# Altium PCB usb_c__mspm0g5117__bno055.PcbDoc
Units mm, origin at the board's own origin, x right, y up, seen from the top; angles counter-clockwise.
Board outline 68 x 40 mm, 2 copper layers (Top, Bottom), stack 0 mm thick; 42 components, 34 nets, 214 pads, 84 vias.
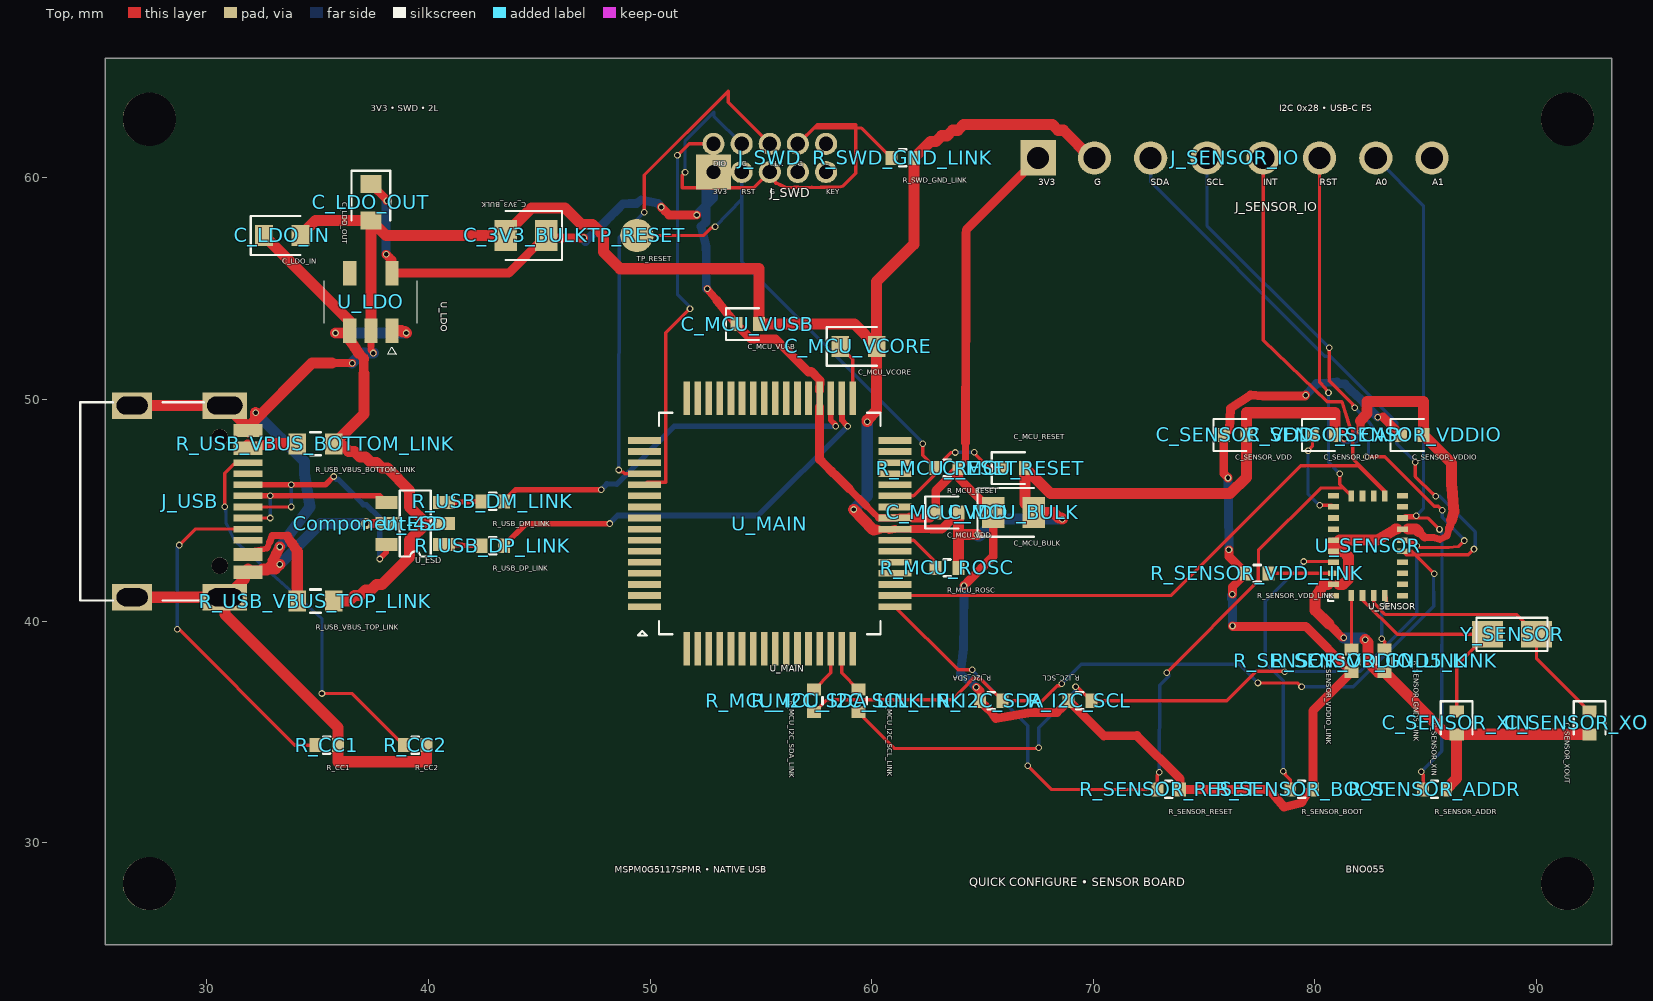
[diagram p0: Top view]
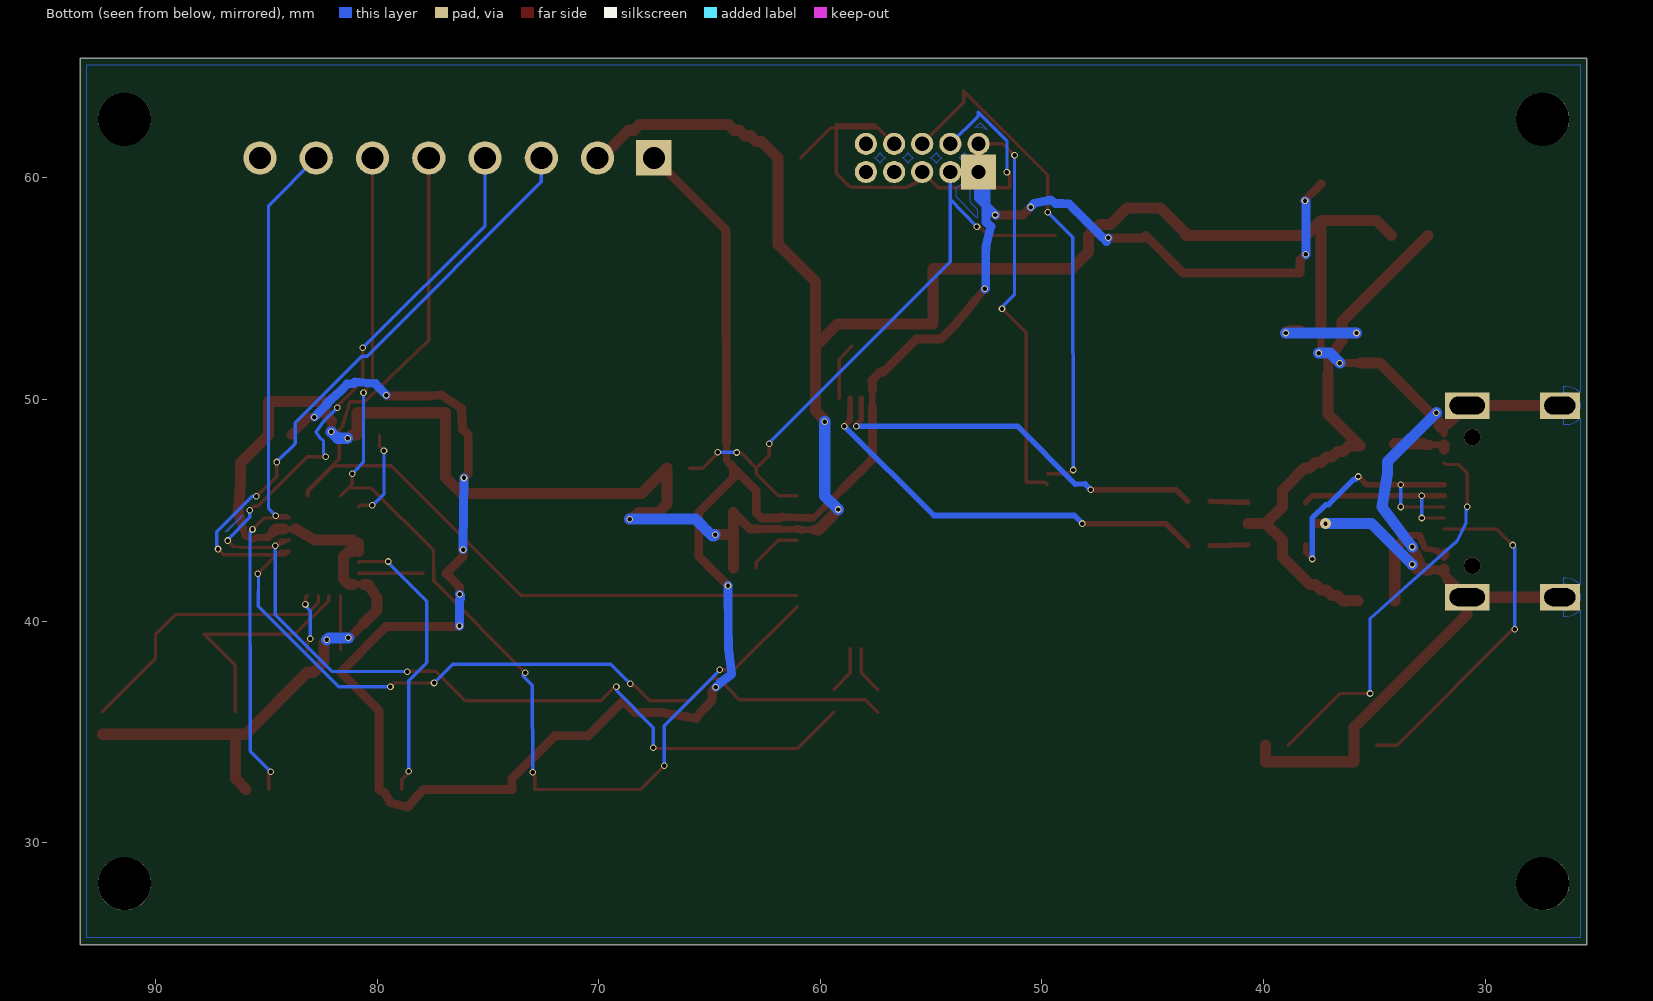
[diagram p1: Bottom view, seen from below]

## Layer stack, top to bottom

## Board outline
25.4,65.4 93.4,65.4 93.4,25.4 25.4,25.4

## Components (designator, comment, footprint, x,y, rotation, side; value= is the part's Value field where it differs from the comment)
C_3V3_BULK "" TSCIRCUIT-2.8500x1.4000mm 44.4,57.4 r180 top
C_LDO_IN "" TSCIRCUIT-2.4500x0.9500mm 33.4,57.4 r0 top
C_LDO_OUT "" TSCIRCUIT-0.9500x2.4500mm 37.4,58.9 r270 top
C_MCU_BULK "" TSCIRCUIT-2.8500x1.4000mm 66.4,44.9 r0 top
C_MCU_RESET "" TSCIRCUIT-1.5600x0.6400mm 66.4,46.9 r0 top
C_MCU_VCORE "" TSCIRCUIT-2.4500x0.9500mm 59.4,52.4 r0 top
C_MCU_VDD "" TSCIRCUIT-1.5600x0.6400mm 63.4,44.9 r0 top
C_MCU_VUSB "" TSCIRCUIT-1.5600x0.6400mm 54.4,53.4 r0 top
C_SENSOR_CAP "" TSCIRCUIT-1.5600x0.6400mm 80.4,48.4 r0 top
C_SENSOR_VDD "" TSCIRCUIT-1.5600x0.6400mm 76.4,48.4 r0 top
C_SENSOR_VDDIO "" TSCIRCUIT-1.5600x0.6400mm 84.4,48.4 r0 top
C_SENSOR_XIN "" TSCIRCUIT-0.6400x1.5600mm 86.4,35.4 r270 top
C_SENSOR_XOUT "" TSCIRCUIT-0.6400x1.5600mm 92.4,35.4 r270 top
Component-42 "" TSCIRCUIT-0.5000x0.5000mm 37.2,44.4 r0 top
J_SENSOR_IO "" TSCIRCUIT-19.2800x1.5000mm 76.4,60.9 r0 top
J_SWD "" TSCIRCUIT-6.0800x2.2700mm 55.4,60.9 r0 top
J_USB "" TSCIRCUIT-6.7732x9.8502mm 29.112,45.4 r90 top
R_CC1 "" TSCIRCUIT-1.5600x0.6400mm 35.4,34.4 r0 top
R_CC2 "" TSCIRCUIT-1.5600x0.6400mm 39.4,34.4 r0 top
R_I2C_SCL "" TSCIRCUIT-1.5600x0.6400mm 69.4,36.4 r180 top
R_I2C_SDA "" TSCIRCUIT-1.5600x0.6400mm 65.4,36.4 r180 top
R_MCU_I2C_SCL_LINK "" TSCIRCUIT-0.6400x1.5600mm 59.4,36.4 r270 top
R_MCU_I2C_SDA_LINK "" TSCIRCUIT-0.6400x1.5600mm 57.4,36.4 r270 top
R_MCU_RESET "" TSCIRCUIT-1.5600x0.6400mm 63.4,46.9 r0 top
R_MCU_ROSC "" TSCIRCUIT-1.5600x0.6400mm 63.4,42.4 r0 top
R_SENSOR_ADDR "" TSCIRCUIT-1.5600x0.6400mm 85.4,32.4 r0 top
R_SENSOR_BOOT "" TSCIRCUIT-1.5600x0.6400mm 79.4,32.4 r0 top
R_SENSOR_GND5_LINK "" TSCIRCUIT-0.6400x1.5600mm 83.15,38.2 r270 top
R_SENSOR_RESET "" TSCIRCUIT-1.5600x0.6400mm 73.4,32.4 r0 top
R_SENSOR_VDD_LINK "" TSCIRCUIT-1.5600x0.6400mm 77.4,42.15 r0 top
R_SENSOR_VDDIO_LINK "" TSCIRCUIT-0.6400x1.5600mm 81.65,38.2 r270 top
R_SWD_GND_LINK "" TSCIRCUIT-1.5600x0.6400mm 61.4,60.9 r0 top
R_USB_DM_LINK "" TSCIRCUIT-1.5600x0.6400mm 42.9,45.4 r0 top
R_USB_DP_LINK "" TSCIRCUIT-1.5600x0.6400mm 42.9,43.4 r0 top
R_USB_VBUS_BOTTOM_LINK "" TSCIRCUIT-2.4500x0.9500mm 34.9,48 r0 top
R_USB_VBUS_TOP_LINK "" TSCIRCUIT-2.4500x0.9500mm 34.9,40.9 r0 top
TP_RESET "" TSCIRCUIT-1.5000x1.5000mm 49.4,57.4 r0 top
U_ESD "" TSCIRCUIT-3.6000x2.5000mm 39.4,44.4 r0 top
U_LDO "" TSCIRCUIT-2.5000x3.7000mm 37.4,54.4 r270 top
U_MAIN "" TSCIRCUIT-12.8000x12.8000mm 55.4,44.4 r0 top
U_SENSOR "" TSCIRCUIT-3.6260x4.9999mm 82.4,43.4 r0 top
Y_SENSOR "" TSCIRCUIT-3.6000x1.2000mm 88.9,39.4 r0 top

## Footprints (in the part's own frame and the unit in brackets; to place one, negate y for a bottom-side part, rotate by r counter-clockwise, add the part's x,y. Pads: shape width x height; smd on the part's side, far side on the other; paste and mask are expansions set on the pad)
TSCIRCUIT-0.5000x0.5000mm [mm]
TSCIRCUIT-0.6400x1.5600mm [mm]
  rect 0.54x0.64 smd: 1(-0.51,0) 2(0.51,0)
  silkscreen extent -0.98,-0.72 0.51,0.72
TSCIRCUIT-0.9500x2.4500mm [mm]
  rect 0.8x0.95 smd: 1(-0.825,0) 2(0.825,0)
  silkscreen extent -1.43,-0.87 0.82,0.88
TSCIRCUIT-1.5000x1.5000mm [mm]
  round 1.5 smd: 1(0,0)
TSCIRCUIT-1.5600x0.6400mm [mm]
  rect 0.54x0.64 smd: 1(-0.51,0) 2(0.51,0)
  silkscreen extent -0.98,-0.72 0.51,0.72
TSCIRCUIT-2.4500x0.9500mm [mm]
  rect 0.8x0.95 smd: 1(-0.825,0) 2(0.825,0)
  silkscreen extent -1.42,-0.87 0.82,0.87
TSCIRCUIT-2.5000x3.7000mm [mm]
  rect 1.1x0.6 smd: 1(1.3,0.95) 2(1.3,0) 3(1.3,-0.95) 4(-1.3,-0.95) 5(-1.3,0.95)
  silkscreen extent -0.95,-2.1 2.35,2.1
TSCIRCUIT-2.8500x1.4000mm [mm]
  rect 1.025x1.4 smd: 1(-0.913,0) 2(0.913,0)
  silkscreen extent -1.63,-1.1 0.91,1.1
TSCIRCUIT-3.6000x1.2000mm [mm]
  rect 1.4x1.2 smd: 1(-1.1,0) 2(1.1,0)
  silkscreen extent -1.6,-0.75 1.6,0.75
TSCIRCUIT-3.6000x2.5000mm [mm]
  rect 1x0.6 smd: 1(-1.3,-0.95) 2(-1.3,0) 3(-1.3,0.95) 4(1.3,0.95) 5(1.3,0) 6(1.3,-0.95)
  silkscreen extent -0.7,-1.49 0.7,1.49
TSCIRCUIT-3.6260x4.9999mm [mm]
  rect 0.5x0.25 smd: 1(-1.563,-2.25) 2(-1.563,-1.75) 3(-1.563,-1.25) 4(-1.563,-0.75) 5(-1.563,-0.25) 6(-1.563,0.25) 7(-1.563,0.75) 8(-1.563,1.25) 9(-1.563,1.75) 10(-1.563,2.25) 15(1.563,2.25) 16(1.563,1.75) 17(1.563,1.25) 18(1.563,0.75) 19(1.563,0.25) 20(1.563,-0.25) 21(1.563,-0.75) 22(1.563,-1.25) 23(1.563,-1.75) 24(1.563,-2.25)
  rect 0.25x0.5 smd: 11(-0.75,2.25) 12(-0.25,2.25) 13(0.25,2.25) 14(0.75,2.25) 25(0.75,-2.25) 26(0.25,-2.25) 27(-0.25,-2.25) 28(-0.75,-2.25)
  silkscreen extent -1.81,-2.5 -1.56,-2.25
TSCIRCUIT-6.0800x2.2700mm [mm]
  rect 1.6x1.6 hole 0.65: 1(-2.54,-0.635)
  round 1 hole 0.65: 2(-2.54,0.635) 3(-1.27,0.635) 4(0,0.635) 5(1.27,0.635) 6(2.54,0.635) 7(2.54,-0.635) 8(1.27,-0.635) 9(0,-0.635) 10(-1.27,-0.635)
TSCIRCUIT-6.7732x9.8502mm [mm]
  rect 0.3x1.3 smd: 1(-3.35,-2.737) 2(-3.05,-2.737) 3(-2.55,-2.737) 4(-2.25,-2.737) 5(-1.75,-2.737) 6(-1.25,-2.737) 7(-0.75,-2.737) 8(-0.25,-2.737) 9(0.25,-2.737) 10(0.75,-2.737) 11(1.25,-2.737) 12(1.75,-2.737) 13(2.55,-2.737) 14(2.25,-2.737) 15(3.35,-2.737) 16(3.05,-2.737)
  rect 1.2x2 hole 0.8 slot 1.6 at 90 deg: 17(-4.325,-1.693) 18(4.325,-1.693)
  rect 1.2x1.8 hole 0.8 slot 1.4 at 90 deg: 19(4.325,2.487) 20(-4.325,2.487)
  round 0.75 hole 0.75 unplated: NPTH-1(-2.9,-1.468) NPTH-2(2.9,-1.468)
  silkscreen extent -4.47,-0.75 4.47,4.83
TSCIRCUIT-12.8000x12.8000mm [mm]
  rect 1.5x0.3 smd: 1(-5.65,-3.75) 2(-5.65,-3.25) 3(-5.65,-2.75) 4(-5.65,-2.25) 5(-5.65,-1.75) 6(-5.65,-1.25) 7(-5.65,-0.75) 8(-5.65,-0.25) 9(-5.65,0.25) 10(-5.65,0.75) 11(-5.65,1.25) 12(-5.65,1.75) 13(-5.65,2.25) 14(-5.65,2.75) 15(-5.65,3.25) 16(-5.65,3.75) 33(5.65,3.75) 34(5.65,3.25) 35(5.65,2.75) 36(5.65,2.25) 37(5.65,1.75) 38(5.65,1.25) 39(5.65,0.75) 40(5.65,0.25) 41(5.65,-0.25) 42(5.65,-0.75) 43(5.65,-1.25) 44(5.65,-1.75) 45(5.65,-2.25) 46(5.65,-2.75) 47(5.65,-3.25) 48(5.65,-3.75)
  rect 0.3x1.5 smd: 17(-3.75,5.65) 18(-3.25,5.65) 19(-2.75,5.65) 20(-2.25,5.65) 21(-1.75,5.65) 22(-1.25,5.65) 23(-0.75,5.65) 24(-0.25,5.65) 25(0.25,5.65) 26(0.75,5.65) 27(1.25,5.65) 28(1.75,5.65) 29(2.25,5.65) 30(2.75,5.65) 31(3.25,5.65) 32(3.75,5.65) 49(3.75,-5.65) 50(3.25,-5.65) 51(2.75,-5.65) 52(2.25,-5.65) 53(1.75,-5.65) 54(1.25,-5.65) 55(0.75,-5.65) 56(0.25,-5.65) 57(-0.25,-5.65) 58(-0.75,-5.65) 59(-1.25,-5.65) 60(-1.75,-5.65) 61(-2.25,-5.65) 62(-2.75,-5.65) 63(-3.25,-5.65) 64(-3.75,-5.65)
  silkscreen extent -5.95,-5.05 5,5
TSCIRCUIT-19.2800x1.5000mm [mm]
  rect 1.6x1.6 hole 1: 1(-8.89,0)
  round 1.5 hole 1: 2(-6.35,0) 3(-3.81,0) 4(-1.27,0) 5(1.27,0) 6(3.81,0) 7(6.35,0) 8(8.89,0)

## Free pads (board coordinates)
  round 2.4 hole 2.4 unplated: NPTH-3(27.4,28.15) NPTH-4(91.4,28.15) NPTH-5(27.4,62.65) NPTH-6(91.4,62.65)

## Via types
v1: diameter 0.3, hole 0.2, Top to Bottom, 83 vias
v2: diameter 0.5, hole 0.2, Top to Bottom, 1 vias

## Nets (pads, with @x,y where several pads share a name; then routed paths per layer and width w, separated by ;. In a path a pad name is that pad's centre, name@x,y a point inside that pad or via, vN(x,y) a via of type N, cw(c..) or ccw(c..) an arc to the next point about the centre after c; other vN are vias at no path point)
".J_SWD > .pin2 to .U_MAIN > .pin12": J_SWD.2 U_MAIN.12 | length 18.3
  Top w0.15: U_MAIN.12 49.858,46.258 50.703,46.258 50.703,53.005 v1(51.799,54.101) ; v1(51.234,61.022) 51.284,61.072 51.302,61.072 51.765,61.535 J_SWD.2
  Bottom w0.15: v1(51.234,61.022) 51.234,54.753 51.75,54.237 51.75,54.15 v1(51.799,54.101)
".J_SWD > .pin4 to .U_MAIN > .pin13": J_SWD.4 U_MAIN.13 | length 23.6
  Top w0.15: v1(48.583,46.817) 48.677,46.723 48.78,46.723 48.854,46.65 U_MAIN.13 ; v1(49.737,58.448) 49.737,60.13 53.527,63.92 53.527,63.408 J_SWD.4
  Bottom w0.15: v1(48.583,46.817) 48.6,57.319 49.646,58.365 49.646,58.406 v1(49.737,58.448)
".U_MAIN > .pin42 to .R_MCU_ROSC > .pin1": R_MCU_ROSC.1 U_MAIN.42 | length 2.5
  Top w0.15: U_MAIN.42 61.89,43.65 62.89,42.65 R_MCU_ROSC.1
".U_SENSOR > .CAP to .C_SENSOR_CAP > .pin1": C_SENSOR_CAP.1 U_SENSOR.9 | length 4.1
  Top w0.15: v1(79.693,47.678) 79.725,47.71 79.725,47.718 79.89,47.883 C_SENSOR_CAP.1 ; v1(80.214,45.222) 80.765,45.222 U_SENSOR.9
  Bottom w0.15: v1(79.693,47.678) 79.693,45.723 80.078,45.339 80.097,45.339 v1(80.214,45.222)
BNO055_GND5_LOCAL: R_SENSOR_GND5_LINK.1 U_SENSOR.25 | length 2.6
  Top w0.15: v1(83.024,39.198) 83.056,39.166 83.15,39.072 R_SENSOR_GND5_LINK.1 ; U_SENSOR.25 83.236,41.064 v1(83.236,40.749)
  Bottom w0.15: v1(83.024,39.198) 83.024,40.468 83.186,40.63 83.186,40.699 v1(83.236,40.749)
BNO055_VDD_LOCAL: R_SENSOR_VDD_LINK.2 U_SENSOR.3 | length 2.9
  Top w0.15: R_SENSOR_VDD_LINK.2 U_SENSOR.3@80.837,42.15
BNO055_VDDIO_LOCAL: R_SENSOR_VDDIO_LINK.1 U_SENSOR.28 | length 2.4
  Top w0.15: R_SENSOR_VDDIO_LINK.1 U_SENSOR.28
GND: C_3V3_BULK.2 C_LDO_IN.2 C_LDO_OUT.2 C_MCU_BULK.2 C_MCU_RESET.2 C_MCU_VCORE.2 C_MCU_VDD.2 C_MCU_VUSB.2 C_SENSOR_CAP.2 C_SENSOR_VDD.2 C_SENSOR_VDDIO.2 C_SENSOR_XIN.2 C_SENSOR_XOUT.2 J_SENSOR_IO.2 J_USB.1 J_USB.2 J_USB.15 J_USB.16 J_USB.17 J_USB.18 J_USB.19 J_USB.20 R_CC1.2 R_CC2.2 R_MCU_ROSC.2 R_SENSOR_ADDR.2 R_SENSOR_GND5_LINK.2 R_SWD_GND_LINK.2 U_ESD.2 U_LDO.2 U_MAIN.41 U_SENSOR.2 U_SENSOR.5 U_SENSOR.6 U_SENSOR.18 | length 190.9
  Top w0.25: U_SENSOR.2@80.587,41.65 U_SENSOR.2 U_SENSOR.2@81.087,41.65 ; U_SENSOR.5 U_SENSOR.5@81.087,43.15 ; 80.837,43.525 U_SENSOR.6 80.931,43.65 81.024,43.65 81.087,43.65 81.118,43.65 ; U_SENSOR.18@83.713,44.15 U_SENSOR.18 ; U_SENSOR.18 84.213,44.15
  Top w0.275: J_USB.16 32.2,48.801 32.2,49.1
  Top w0.3: J_USB.1@31.699,41.9 J_USB.1 J_USB.1@31.849,42.2 ; J_USB.15@31.699,48.9 J_USB.15 ; J_USB.16@31.849,48.6 J_USB.15 ; J_USB.2@31.946,42.332 J_USB.2 32,42.2 32.4,42.3 J_USB.2@32.499,42.3 ; J_USB.15@31.999,48.9 J_USB.15 ; J_USB.2@32.037,42.35 32.13,42.35 32.224,42.35 32.318,42.35 32.411,42.35 J_USB.2@32.499,42.35 ; U_MAIN.41 61.144,44.15 61.238,44.15 61.331,44.15 61.425,44.15 61.519,44.15 61.613,44.15 61.706,44.15 61.8,44.15
  Top w0.301: J_USB.2@31.946,42.332 J_USB.2@32.037,42.35
  Top w0.302: U_MAIN.41@60.425,44.117 60.55,44.118 60.675,44.117 U_MAIN.41@60.797,44.11
  Top w0.312: 85.65,43.681 85.963,43.837 86.067,44.202
  Top w0.323: U_MAIN.41@60.3,44.115 U_MAIN.41@60.425,44.117
  Top w0.325: J_USB.16 J_USB.16@31.849,48.6 ; U_LDO.2 37.4,52.664 37.4,52.228 37.49,52.137 37.49,52.117 v1(37.513,52.094) ; v1@81.231,39.265 81.265,39.265 v1(81.297,39.243) ; 84.954,43.771 85.36,43.77 85.65,43.681
  Top w0.35: 35.652,51.645 36.103,51.643 v1(36.555,51.641)
  Top w0.375: U_MAIN.41@60.797,44.11 U_MAIN.41 ; 61.8,44.15 62.253,44.15 62.707,44.15 ; 80.934,39.562 v1@81.231,39.265 ; C_SENSOR_CAP.2@81.16,48.4 81.182,48.4 v1(81.331,48.251) ; 82.059,49.028 v1(82.072,48.535) ; 84.67,44.048 84.954,43.771 ; 86.067,44.202 86.171,44.567
  Top w0.4: 37.2,44.4 U_ESD.2@37.6,44.4 ; 62.707,44.15 63.16,44.15 63.41,44.4 63.66,44.65 C_MCU_VDD.2 ; 80.637,39.859 80.934,39.562
  Top w0.425: 60.175,44.12 60.3,44.115
  Top w0.475: 32.961,42.561 32.961,42.715 33.123,43.029 v1(33.284,43.344) ; 60.093,44.12 60.175,44.12
  Top w0.5: J_USB.20 J_USB.17 30.806,40.289 35.91,35.185 R_CC1.2 35.91,33.65 39.91,33.65 R_CC2.2 ; J_USB.19 J_USB.18 ; J_USB.17 30.874,41.075 31.474,41.675 31.699,41.9 ; J_USB.18 30.874,49.725 31.474,49.125 31.699,48.9 ; J_USB.1@31.849,42.2 J_USB.2 ; 31.999,48.9 34.744,51.645 35.652,51.645 ; 32.2,49.1 v1(32.2,49.4) ; 32.499,42.3 32.7,42.3 32.8,42.4 32.961,42.561 ; 32.499,42.35 32.505,42.35 32.599,42.35 33.081,42.35 v1(33.285,42.554) ; C_LDO_IN.2 34.9,58.075 C_LDO_OUT.2 ; U_LDO.2 C_LDO_OUT.2 ; v1(59.19,45.033) 60.045,44.133 60.093,44.12 ; v1(59.8,49) 59.8,49.076 60.225,49.501 C_MCU_VCORE.2 ; R_MCU_ROSC.2 C_MCU_VDD.2 63.91,43.902 v1(64.745,43.902) ; v1(68.6,44.6) 68.555,44.645 68.457,44.645 68.201,44.9 67.757,44.9 C_MCU_BULK.2 66.91,45.303 C_MCU_RESET.2 68.061,45.749 76.179,45.749 76.91,46.481 C_SENSOR_VDD.2 76.91,49.4 80.91,49.4 C_SENSOR_CAP.2 C_SENSOR_CAP.2@81.16,48.4 ; J_SENSOR_IO.2 69.9,60.9 68.65,62.15 68.4,62.15 68.15,62.4 64.15,62.4 63.9,62.15 63.65,62.15 63.4,61.9 63.15,61.9 62.9,61.65 62.65,61.65 62.65,61.64 62.579,61.569 62.244,61.234 R_SWD_GND_LINK.2 61.91,57.006 60.225,55.321 60.225,54.834 60.225,54.347 60.225,53.86 60.225,53.374 60.225,52.887 C_MCU_VCORE.2 ; 80.587,41.65 80.4,41.65 80.01,41.051 80.01,40.487 80.637,39.859 ; U_SENSOR.5 80.837,43.275 80.837,43.525 ; 81.087,41.65 81.275,41.65 81.525,41.9 81.525,42.9 81.275,43.15 81.087,43.15 ; 81.118,43.65 81.212,43.65 81.306,43.65 81.399,43.65 81.493,43.65 81.587,43.65 81.994,43.65 82.401,43.65 82.807,43.65 83.65,44.15 U_SENSOR.18@83.713,44.15 ; 82.059,49.028 82.355,49.37 82.355,49.9 84.91,49.9 C_SENSOR_VDDIO.2 85.225,48.085 85.54,47.77 85.855,47.455 86.171,47.139 86.171,46.658 86.171,46.176 86.205,45.761 86.24,45.346 86.275,44.931 86.171,44.567 ; v1(82.274,39.155) 82.4,39.029 82.4,38.15 82.86,37.69 R_SENSOR_GND5_LINK.2 85.95,34.89 C_SENSOR_XIN.2 ; 84.213,44.15 84.568,44.15 84.67,44.048 ; R_SENSOR_ADDR.2 86.4,32.89 C_SENSOR_XIN.2 ; C_SENSOR_XOUT.2 C_SENSOR_XIN.2 ; C_LDO_OUT.2 38.075,57.4 C_3V3_BULK.2 43.488,57.487 44.65,58.65 46.15,58.65 46.9,57.9 47.4,57.9 47.9,57.4 47.9,56.65 48.65,55.9 51.15,55.9 54.91,55.9 C_MCU_VUSB.2 59.225,53.4 C_MCU_VCORE.2
  Bottom w0.5: v1(32.2,49.4) 34.4,47.2 34.4,46.65 34.65,45.15 v1(33.284,43.344) ; v1(33.285,42.554) 35.131,44.4 37.2,44.4 ; v1(36.555,51.641) 37.008,52.094 v1(37.513,52.094) ; v1(59.19,45.033) 59.8,45.643 v1(59.8,49) ; v1(64.745,43.902) 64.808,43.839 64.871,43.839 65.124,44.093 65.378,44.346 65.632,44.6 66.126,44.6 66.621,44.6 67.116,44.6 67.611,44.6 68.105,44.6 v1(68.6,44.6) ; v1(81.297,39.243) 82.186,39.243 v1(82.274,39.155) ; v1(81.331,48.251) 81.788,48.251 v1(82.072,48.535)
MAIN_RESET: C_MCU_RESET.1 J_SWD.10 R_MCU_RESET.1 TP_RESET.1 U_MAIN.38 | length 29.8
  Top w0.15: TP_RESET.1 52.417,57.4 52.758,57.741 52.827,57.741 v1(52.931,57.795) ; U_MAIN.38 61.889,45.65 62.89,46.651 R_MCU_RESET.1 ; v1(62.306,48.008) 62.306,47.484 R_MCU_RESET.1 ; v1(63.774,47.607) 63.597,47.607 R_MCU_RESET.1 ; v1(64.635,47.62) 64.659,47.561 64.659,47.549 65.308,46.9 C_MCU_RESET.1
  Bottom w0.15: v1(52.931,57.795) 54.13,59.044 J_SWD.10 54.13,56.225 62.233,48.122 62.233,48.081 v1(62.306,48.008) ; v1(63.774,47.607) 63.782,47.615 63.853,47.615 63.858,47.62 v1(64.635,47.62)
MCU_I2C_SCL_LOCAL: R_MCU_I2C_SCL_LINK.1 U_MAIN.50 | length 2.2
  Top w0.15: U_MAIN.50 58.65,37.66 R_MCU_I2C_SCL_LINK.1
MCU_I2C_SDA_LOCAL: R_MCU_I2C_SDA_LINK.1 U_MAIN.51 | length 2.2
  Top w0.15: R_MCU_I2C_SDA_LINK.1 58.15,37.66 U_MAIN.51
MSPM0_VCORE: C_MCU_VCORE.1 U_MAIN.32 | length 2.6
  Top w0.15: C_MCU_VCORE.1 59.15,51.825 U_MAIN.32
SENSOR_ADDR0: J_SENSOR_IO.7 R_SENSOR_ADDR.1 U_SENSOR.17 | length 31.9
  Top w0.15: v1(84.576,44.752) 84.065,44.752 U_SENSOR.17 85.107,44.65 v1(85.624,44.133) ; v1(84.8,33.2) 84.829,33.171 84.829,33.125 84.89,33.063 R_SENSOR_ADDR.1
  Bottom w0.15: J_SENSOR_IO.7 84.902,58.748 84.902,45.196 84.902,45.078 84.641,44.817 v1(84.576,44.752) ; v1(84.8,33.2) 85.733,34.133 85.735,43.813 85.733,44.018 85.702,44.049 85.702,44.055 v1(85.624,44.133)
SENSOR_ADDR1: J_SENSOR_IO.8
SENSOR_BOOT: R_SENSOR_BOOT.1 U_SENSOR.4 | length 12.8
  Top w0.15: v1(78.58,33.219) 78.671,33.128 78.671,33.059 78.89,32.84 R_SENSOR_BOOT.1 ; v1(79.506,42.686) 80.801,42.686 U_SENSOR.4
  Bottom w0.15: v1(78.58,33.219) 78.578,37.3 77.755,38.126 77.755,40.893 79.431,42.568 79.431,42.611 v1(79.506,42.686)
SENSOR_INT: J_SENSOR_IO.5 U_MAIN.47 U_SENSOR.14 | length 43.1
  Top w0.15: U_MAIN.47 73.505,41.152 79.37,47.015 81.963,47.014 83.115,45.863 83.115,45.685 U_SENSOR.14 83.15,45.877 81.705,47.322 81.705,48.635 81.573,48.767 81.225,49.9 80.55,49.9 77.67,52.67 J_SENSOR_IO.5
SENSOR_RESET: J_SENSOR_IO.6 R_SENSOR_RESET.1 U_MAIN.48 U_SENSOR.11 | length 50.4
  Top w0.15: U_MAIN.48 63.897,37.803 v1(64.543,37.803) ; v1(67.036,33.469) 67.069,33.436 68.105,32.4 R_SENSOR_RESET.1 72.89,33.037 72.97,33.117 72.97,33.17 v1(72.974,33.174) ; v1(73.31,37.671) 77.446,41.819 77.455,43.199 80.263,46.003 81.297,46.003 U_SENSOR.11 81.13,46.17 v1(81.13,46.645) ; J_SENSOR_IO.6 80.21,50.769 80.471,50.508 80.471,50.499 v1(80.616,50.307)
  Bottom w0.15: v1(64.543,37.803) 64.606,37.712 67.036,35.282 v1(67.036,33.469) ; v1(72.974,33.174) 73,37.104 73.421,37.525 73.421,37.56 v1(73.31,37.671) ; v1(80.616,50.307) 80.616,47.164 81.011,46.769 81.011,46.764 v1(81.13,46.645)
SENSOR_SCL: J_SENSOR_IO.4 R_I2C_SCL.1 R_MCU_I2C_SCL_LINK.2 U_SENSOR.19 | length 59.4
  Top w0.15: R_MCU_I2C_SCL_LINK.2 61.043,34.247 67.469,34.247 67.503,34.247 v1(67.54,34.284) ; v1(69.2,37.028) 69.282,37.028 R_I2C_SCL.1 76.026,36.4 77.358,37.732 78.554,37.732 78.562,37.741 78.612,37.741 v1(78.64,37.719) ; v1(80.643,52.336) 80.643,50.85 81.712,49.78 81.712,49.709 v1(81.795,49.626) ; v1(82.319,47.42) 83.148,47.42 85.384,45.184 85.574,45.184 v1(85.75,45.008) ; v1(84.603,43.403) 84.35,43.65 U_SENSOR.19 84.661,43.323 86.037,43.321 86.476,43.361 v1(86.748,43.633)
  Bottom w0.15: v1(67.54,34.284) 67.54,35.189 69.197,36.847 69.197,37.025 v1(69.2,37.028) ; J_SENSOR_IO.4 75.13,57.849 80.554,52.425 v1(80.643,52.336) ; v1(78.64,37.719) 82.037,37.719 84.597,40.279 84.6,43.397 v1(84.603,43.403) ; v1(81.795,49.626) 82.424,48.998 82.761,48.536 82.588,48.278 82.424,48.143 82.423,47.566 82.303,47.446 82.303,47.436 v1(82.319,47.42) ; v1(85.75,45.008) 85.75,44.675 86.748,43.677 v1(86.748,43.633)
SENSOR_SDA: J_SENSOR_IO.3 R_I2C_SDA.1 R_MCU_I2C_SDA_LINK.2 U_SENSOR.20 | length 62.3
  Top w0.15: R_MCU_I2C_SDA_LINK.2 57.962,36.452 59.667,36.449 63.656,36.452 64.575,37.413 64.952,37.358 R_I2C_SDA.1 67.69,36.4 68.376,37.086 68.491,37.086 v1(68.582,37.177) ; v1(77.431,37.206) 79.205,37.206 79.363,37.048 79.389,37.048 v1(79.4,37.037) ; v1(84.537,47.175) 84.537,46.523 85.312,45.748 85.339,45.748 v1(85.461,45.626) ; v1(85.395,42.133) 84.378,43.147 U_SENSOR.20 84.118,42.995 84.395,42.995 86.928,42.995 v1(87.181,43.248)
  Bottom w0.15: v1(68.582,37.177) 69.454,38.049 76.469,38.049 76.588,38.049 77.386,37.251 v1(77.431,37.206) ; J_SENSOR_IO.3 72.59,59.819 80.452,51.957 80.689,51.957 83.703,48.942 83.703,48.009 84.456,47.256 v1(84.537,47.175) ; v1(79.4,37.037) 81.726,37.034 85.359,40.667 85.356,42.073 85.407,42.124 v1(85.395,42.133) ; v1(85.461,45.626) 85.63,45.626 87.237,44.019 87.237,43.304 87.191,43.258 v1(87.181,43.248)
SENSOR_XIN: C_SENSOR_XIN.1 U_SENSOR.27 Y_SENSOR.1 | length 10.6
  Top w0.15: U_SENSOR.27 82.192,41.108 82.19,40.916 83.708,39.399 Y_SENSOR.1 86.4,38 C_SENSOR_XIN.1
SENSOR_XOUT: C_SENSOR_XOUT.1 U_SENSOR.26 Y_SENSOR.2 | length 12.7
  Top w0.15: U_SENSOR.26 82.651,40.83 83.187,40.295 89.107,40.293 Y_SENSOR.2 90,38.31 C_SENSOR_XOUT.1
swd-ground-1-to-2: J_SWD.3 J_SWD.5 J_SWD.9 R_SWD_GND_LINK.1 | length 24.9
  Top w0.15: v1(51.576,60.261) 51.439,60.124 51.439,60.118 51.446,60.111 51.446,59.551 54.686,59.551 J_SWD.9 55.675,59.765 55.7,59.765 55.91,59.667 56.092,59.578 56.3,59.569 56.501,59.575 56.7,59.575 56.9,59.568 57.3,59.578 57.499,59.567 57.7,59.575 57.9,59.575 58.1,59.573 58.505,59.575 58.717,59.638 59.277,60.198 59.277,62.405 57.54,62.405 J_SWD.5 57.382,62.247 59.375,62.247 59.543,62.247 R_SWD_GND_LINK.1
  Bottom w0.15: v1(51.576,60.261) 51.576,61.666 52.88,62.97 52.88,62.785 J_SWD.3
usb-dm-device: R_USB_DM_LINK.1 U_ESD.4 | length 1.7
  Top w0.25: U_ESD.4 R_USB_DM_LINK.1
usb-dm-mcu: R_USB_DM_LINK.2 U_MAIN.30 | length 17.7
  Top w0.25: R_USB_DM_LINK.2 43.943,45.933 v1(47.793,45.933) ; U_MAIN.30 58.15,49.076 58.345,48.881 58.345,48.855 v1(58.378,48.798)
  Bottom w0.25: v1(47.793,45.933) 47.826,45.966 48.05,46.19 48.497,46.176 51.094,48.798 v1(58.378,48.798)
usb-dm-port-tie: J_USB.7 J_USB.9 U_ESD.3 | length 9.4
  Top w0.15: J_USB.7 v1(32.85,44.65) ; J_USB.9 v1(32.85,45.65)
  Top w0.25: J_USB.9 37.8,45.65 U_ESD.3
  Bottom w0.15: v1(32.85,44.65) v1(32.85,45.65)
usb-dp-device: R_USB_DP_LINK.1 U_ESD.6 | length 1.7
  Top w0.25: U_ESD.6 R_USB_DP_LINK.1
usb-dp-mcu: R_USB_DP_LINK.2 U_MAIN.31 | length 19.1
  Top w0.25: R_USB_DP_LINK.2 44.41,44.4 v1(48.172,44.4) ; U_MAIN.31 58.66,49.069 58.833,48.876 58.833,48.865 v1(58.918,48.785)
  Bottom w0.25: v1(48.172,44.4) 48.535,44.763 48.577,44.763 54.878,44.763 v1(58.918,48.785)
usb-dp-port-tie: J_USB.8 J_USB.10 U_ESD.1 | length 14.4
  Top w0.15: J_USB.8 v1(33.8,45.15) ; J_USB.10 v1(33.8,46.15)
  Top w0.25: J_USB.10 35.341,46.15 v1(35.715,46.525) ; v1(37.8,42.8) 37.812,42.812 37.812,42.819 38.1,43.107 U_ESD.1
  Bottom w0.15: v1(33.8,45.15) v1(33.8,46.15)
  Bottom w0.25: v1(35.715,46.525) 35.833,46.407 35.911,46.407 37.06,45.258 37.183,45.258 37.8,44.641 v1(37.8,42.8)
USB_CC1: J_USB.6 R_CC1.1 | length 15.6
  Top w0.15: v1(28.666,39.625) 28.712,39.579 28.785,39.579 33.964,34.4 R_CC1.1 ; v1(28.753,43.429) 29.474,44.15 J_USB.6
  Bottom w0.15: v1(28.666,39.625) 28.666,43.338 28.692,43.364 28.692,43.368 v1(28.753,43.429)
USB_CC2: J_USB.12 R_CC2.1 | length 17.7
  Top w0.15: v1(30.806,45.157) 30.804,46.672 31.199,47.069 31.766,47.067 J_USB.12 ; v1(35.19,36.73) 35.191,36.729 35.355,36.729 36.561,36.729 R_CC2.1
  Bottom w0.15: v1(30.806,45.157) 30.848,45.114 30.848,44.93 30.859,44.919 30.859,44.435 31.05,44.05 31.275,43.6 35.19,40.104 v1(35.19,36.73)
USB_VBUS_BOTTOM_LOCAL: J_USB.13 J_USB.14 R_USB_VBUS_BOTTOM_LINK.1 | length 2.5
  Top w0.3: J_USB.14 J_USB.14@31.849,47.8 ; J_USB.13 J_USB.13@32.499,47.95
  Top w0.437: 32.72,47.95 32.769,48
  Top w0.45: 32.499,47.95 32.72,47.95
  Top w0.475: J_USB.13@31.849,47.8 J_USB.13
  Top w0.5: 32.769,48 33.205,48 33.64,48 R_USB_VBUS_BOTTOM_LINK.1
USB_VBUS_TOP_LOCAL: J_USB.3 J_USB.4 R_USB_VBUS_TOP_LINK.1 | length 5.7
  Top w0.275: J_USB.3 32.172,43.173 32.442,43.224 32.712,43.275 32.83,43.565
  Top w0.3: J_USB.3 31.849,43 J_USB.4
  Top w0.325: 32.83,43.565 32.947,43.855 33.362,43.855
  Top w0.35: 33.362,43.855 33.619,43.837
  Top w0.425: 33.619,43.837 33.847,43.49
  Top w0.475: 33.847,43.49 34.075,43.142
  Top w0.5: R_USB_VBUS_TOP_LINK.1 34.075,41.348 34.075,41.797 34.075,42.245 34.075,42.694 34.075,43.142
VBUS5: C_LDO_IN.1 R_USB_VBUS_BOTTOM_LINK.2 R_USB_VBUS_TOP_LINK.2 U_ESD.5 U_LDO.1 U_LDO.3 | length 30.4
  Top w0.437: 36.869,52.072 37.088,51.853 37.08,51.614 37.079,51.161
  Top w0.5: C_LDO_IN.1 36.45,53.525 U_LDO.3 ; R_USB_VBUS_TOP_LINK.2 35.751,40.926 36.232,40.926 36.206,40.9 36.4,40.9 36.65,41.15 36.9,41.15 37.15,41.4 37.4,41.4 37.65,41.65 37.9,41.65 39.15,42.9 39.15,43.65 39.9,44.4 ; v1(35.8,53) 36.35,53 U_LDO.3 ; 36.869,52.072 36.66,52.371 36.452,52.669 U_LDO.3 ; 37.079,51.161 37.079,49.354 R_USB_VBUS_BOTTOM_LINK.2 35.65,47.925 35.65,47.9 36.15,47.9 36.4,47.65 36.65,47.65 36.9,47.4 37.15,47.4 37.4,47.15 37.65,47.15 37.9,46.9 38.15,46.9 39.15,45.9 39.15,45.15 39.9,44.4 ; U_LDO.1 38.787,53.1 38.832,53.056 38.944,53.056 v1(39,53) ; 39.9,44.4 U_ESD.5 39.9,44.4
  Bottom w0.5: v1(35.8,53) v1(39,53)
VCC_3V3: C_3V3_BULK.1 C_LDO_OUT.1 C_MCU_BULK.1 C_MCU_VDD.1 C_MCU_VUSB.1 C_SENSOR_VDD.1 C_SENSOR_VDDIO.1 J_SENSOR_IO.1 J_SWD.1 R_I2C_SCL.2 R_I2C_SDA.2 R_MCU_RESET.2 R_SENSOR_BOOT.2 R_SENSOR_RESET.2 R_SENSOR_VDD_LINK.1 R_SENSOR_VDDIO_LINK.2 U_LDO.5 U_MAIN.29 U_MAIN.40 | length 126.7
  Top w0.275: 59.776,45.183 60.042,44.919 U_MAIN.40@60.307,44.655
  Top w0.3: U_MAIN.29@57.65,49.657 U_MAIN.29 U_MAIN.29@57.65,50.394 ; U_MAIN.40@61.041,44.652 U_MAIN.40 ; R_MCU_RESET.2@64.071,47.078 64.232,47.255 64.233,47.65 64.234,48.044
  Top w0.305: U_MAIN.40@60.307,44.655 60.674,44.654 U_MAIN.40@61.041,44.652
  Top w0.312: v1(82.841,49.201) 83.071,49.219
  Top w0.317: U_MAIN.40@60.703,44.658 60.361,44.67 U_MAIN.40@60.712,44.666
  Top w0.335: U_MAIN.40@60.703,44.658 U_MAIN.40
  Top w0.337: v1(52.576,54.993) 52.795,54.728 53.014,54.462 ; 58.979,45.976 59.245,45.711 59.51,45.447 59.776,45.183
  Top w0.35: U_MAIN.40@60.712,44.666 U_MAIN.40@61.733,44.7
  Top w0.4: C_LDO_OUT.1 38.125,59 v1(38.125,58.965) ; v1(38.088,56.547) 38.232,56.402 38.235,56.402 38.35,56.288 U_LDO.5 43.613,55.7 C_3V3_BULK.1 45.418,57.295 45.815,57.295 46.213,57.295 46.61,57.295 v1(47.007,57.295) ; v1(50.501,58.683) 50.68,58.504 50.859,58.325 51.169,58.325 51.48,58.325 51.79,58.325 v1(52.1,58.325) ; 53.014,54.462 53.233,54.197 53.452,53.931 53.671,53.666 C_MCU_VUSB.1 54.115,53.175 54.339,52.951 54.564,52.726 54.93,52.726 55.296,52.726 55.662,52.726 55.911,52.478 56.159,52.23 56.408,51.981 56.656,51.733 56.905,51.484 57.153,51.236 57.267,51.267 57.667,50.867 U_MAIN.29@57.65,50.394 ; U_MAIN.29@57.65,49.657 57.65,49.263 57.65,48.87 57.65,48.476 57.65,48.083 57.65,47.69 57.651,47.296 57.916,47.032 58.182,46.768 58.448,46.504 58.713,46.24 58.979,45.976 ; U_MAIN.40@61.733,44.7 61.85,44.65 62.64,44.65 C_MCU_VDD.1 62.89,45.88 R_MCU_RESET.2 ; R_MCU_RESET.2@64.071,47.078 R_MCU_RESET.2 ; v1(64.166,41.597) 64.43,41.861 64.695,42.126 64.959,42.39 65.224,42.655 65.488,42.919 65.488,43.315 65.488,43.711 65.488,44.108 65.488,44.504 C_MCU_BULK.1 63.91,46.478 R_MCU_RESET.2 ; 64.234,48.044 64.235,48.438 64.237,48.832 64.238,49.226 64.239,49.62 64.24,50.014 64.242,50.408 64.243,50.803 64.244,51.197 64.245,51.591 64.247,51.985 64.248,52.379 64.249,52.773 64.25,53.167 64.252,53.561 64.253,53.955 64.254,54.35 64.255,54.744 64.257,55.138 64.258,55.532 64.259,55.926 64.26,56.32 64.262,56.714 64.263,57.108 64.264,57.502 64.265,57.655 64.536,57.926 64.806,58.196 65.077,58.467 65.347,58.737 65.617,59.007 65.888,59.278 66.158,59.548 66.428,59.818 66.699,60.089 66.969,60.359 67.24,60.63 J_SENSOR_IO.1 ; v1(64.721,37.012) 64.85,36.883 64.89,36.843 64.89,36.621 R_I2C_SDA.2 65.154,36.136 65.418,35.872 65.6,35.6 67.182,35.872 67.575,35.872 67.969,35.872 68.362,35.872 68.626,36.136 R_I2C_SCL.2 70.47,34.82 71.966,34.828 73.927,32.885 R_SENSOR_RESET.2 74.309,32.4 74.708,32.4 75.107,32.4 75.506,32.4 75.906,32.4 76.305,32.4 76.704,32.4 77.103,32.4 77.502,32.4 77.901,32.4 78.105,32.195 78.6,31.6 79.4,31.8 79.655,32.24 R_SENSOR_BOOT.2 79.91,35.95 R_SENSOR_VDDIO_LINK.2 79.584,39.756 76.506,39.756 76.304,39.756 v1(76.282,39.778) ; v1(76.082,46.458) 76.07,46.47 76.073,46.478 75.89,46.661 C_SENSOR_VDD.1 76.142,48.652 76.2,49.6 77.1,50.2 77.652,50.162 78.017,50.162 78.382,50.162 78.746,50.162 79.111,50.162 79.476,50.162 79.554,50.162 v1(79.59,50.198) ; v1(76.123,43.217) 76.12,42.92 R_SENSOR_VDD_LINK.1 76.278,41.538 v1(76.278,41.207) ; 83.071,49.219 83.344,48.946 83.617,48.673 C_SENSOR_VDDIO.1
  Bottom w0.4: v1(38.088,56.547) 38.088,58.797 38.088,58.928 v1(38.125,58.965) ; v1(47.007,57.295) 47.085,57.217 47.085,57.134 47.367,57.416 47.649,57.698 47.931,57.98 48.213,58.262 48.495,58.544 48.777,58.826 49.063,58.849 49.387,58.85 49.6,59 50.358,58.851 v1(50.501,58.683) ; v1(52.1,58.325) 52.104,58.329 52.356,58.581 52.608,58.833 52.86,59.085 52.86,59.478 52.86,59.872 J_SWD.1 52.707,60.112 52.554,59.959 52.526,59.892 52.526,59.517 52.527,59.142 52.527,58.767 52.528,58.392 52.528,58.016 52.3,57.8 52.53,56.891 52.531,56.516 52.531,56.14 52.532,55.765 52.532,55.39 52.533,55.015 v1(52.576,54.993) ; v1(64.166,41.597) 64.164,41.531 64.162,41.135 64.159,40.738 64.157,40.342 64.154,39.945 64.152,39.549 64.149,39.153 64.147,38.756 64,37.6 64.527,37.197 v1(64.721,37.012) ; v1(76.082,46.458) 76.12,43.421 v1(76.123,43.217) ; v1(76.278,41.207) 76.234,41.163 76.234,41.007 76.282,40.959 v1(76.282,39.778) ; v1(79.59,50.198) 79.834,50.455 80.077,50.712 81,50.8 81.04,50.707 81.361,50.705 81.361,50.681 81.643,50.399 82.3,49.8 82.207,49.835 82.489,49.553 82.77,49.272 v1(82.841,49.201)
pads on no net: J_SWD.6 J_SWD.7 J_SWD.8 J_USB.5 J_USB.11 J_USB.NPTH-1 J_USB.NPTH-2 U_LDO.4 U_MAIN.1 U_MAIN.2 U_MAIN.3 U_MAIN.4 U_MAIN.5 U_MAIN.6 U_MAIN.7 U_MAIN.8 U_MAIN.9 U_MAIN.10 U_MAIN.11 U_MAIN.14 U_MAIN.15 U_MAIN.16 U_MAIN.17 U_MAIN.18 U_MAIN.19 U_MAIN.20 U_MAIN.21 U_MAIN.22 U_MAIN.23 U_MAIN.24 U_MAIN.25 U_MAIN.26 U_MAIN.27 U_MAIN.28 U_MAIN.33 U_MAIN.34 U_MAIN.35 U_MAIN.36 U_MAIN.37 U_MAIN.39 U_MAIN.43 U_MAIN.44 U_MAIN.45 U_MAIN.46 U_MAIN.49 U_MAIN.52 U_MAIN.53 U_MAIN.54 U_MAIN.55 U_MAIN.56 U_MAIN.57 U_MAIN.58 U_MAIN.59 U_MAIN.60 U_MAIN.61 U_MAIN.62 U_MAIN.63 U_MAIN.64 U_SENSOR.1 U_SENSOR.7 U_SENSOR.8 U_SENSOR.10 U_SENSOR.12 U_SENSOR.13 U_SENSOR.15 U_SENSOR.16 U_SENSOR.21 U_SENSOR.22 U_SENSOR.23 U_SENSOR.24
copper on no net:
  other v2: 37.2,44.4

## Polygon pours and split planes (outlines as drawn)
GND on Bottom (solid): 93.1,65.1 25.7,65.1 25.7,50.296 25.725,50.326 25.854,50.432 26.001,50.51 26.16,50.559 26.326,50.575 26.476,50.575 26.476,50.325 26.326,50.325 26.209,50.314 26.096,50.279 25.993,50.224 25.902,50.149 25.827,50.058 25.772,49.955 25.747,49.875 25.7,49.875 25.7,49.575 25.747,49.575 25.772,49.496 25.827,49.392 25.902,49.301 25.993,49.226 26.096,49.171 26.209,49.137 26.326,49.125 26.476,49.125 26.476,48.875 26.326,48.875 26.16,48.891 26.001,48.94 25.854,49.018 25.725,49.124 25.7,49.154 25.7,41.646 25.725,41.676 25.854,41.782 26.001,41.86 26.16,41.909 26.326,41.925 26.476,41.925 26.476,41.675 26.326,41.675 26.209,41.663 26.096,41.629 25.993,41.574 25.902,41.499 25.827,41.408 25.772,41.304 25.747,41.225 25.7,41.225 25.7,40.925 25.747,40.925 25.772,40.845 25.827,40.742 25.902,40.651 25.993,40.576 26.096,40.521 26.209,40.486 26.326,40.475 26.476,40.475 26.476,40.225 26.326,40.225 26.16,40.241 26.001,40.29 25.854,40.368 25.725,40.474 25.7,40.504 25.7,25.7 93.1,25.7
GND on Bottom (solid): 52.787,62.489 52.474,62.175 52.573,62.228 52.714,62.271 52.86,62.285 53.005,62.271
GND on Bottom (solid): 53.495,61.14 53.484,61.118 53.399,61.015 53.591,61.015 53.506,61.118
GND on Bottom (solid): 53.61,60.996 53.61,60.804 53.713,60.889 53.735,60.9 53.713,60.911
GND on Bottom (solid): 57.305,61.14 57.294,61.118 57.2,61.005 57.087,60.911 57.065,60.9 57.087,60.889 57.2,60.795 57.294,60.682 57.305,60.66 57.316,60.682 57.41,60.795 57.523,60.889 57.545,60.9 57.523,60.911 57.41,61.005 57.316,61.118
GND on Bottom (solid): 56.035,61.14 56.024,61.118 55.93,61.005 55.817,60.911 55.795,60.9 55.817,60.889 55.93,60.795 56.024,60.682 56.035,60.66 56.046,60.682 56.14,60.795 56.253,60.889 56.275,60.9 56.253,60.911 56.14,61.005 56.046,61.118
GND on Bottom (solid): 54.765,61.14 54.754,61.118 54.66,61.005 54.547,60.911 54.525,60.9 54.547,60.889 54.66,60.795 54.754,60.682 54.765,60.66 54.776,60.682 54.87,60.795 54.983,60.889 55.005,60.9 54.983,60.911 54.87,61.005 54.776,61.118
GND on Bottom (solid): 53.61,59.726 53.61,59.515 53.26,59.515 53.26,59.478 53.26,59.085 53.252,59.007 53.23,58.932 53.193,58.863 53.143,58.802 52.928,58.587 52.928,58.392 52.928,58.195 52.931,58.195 52.934,58.195 53.855,59.155 53.855,59.568 53.843,59.572 53.713,59.641
GND on Bottom (solid): 86.082,44.785 86.058,44.756 86.785,44.029 86.826,44.025 86.848,44.019

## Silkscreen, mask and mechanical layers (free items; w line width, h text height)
Top Overlay:
  text "3V3 • SWD • 2L" at 37.4,62.9 h0.48
  text "I2C 0x28 • USB-C FS" at 78.4,62.9 h0.5
  text "MSPM0G5117SPMR • NATIVE USB" at 48.4,28.525 h0.52
  text "BNO055" at 81.4,28.525 h0.55
  text "QUICK CONFIGURE • SENSOR BOARD" at 64.4,27.9 h0.65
